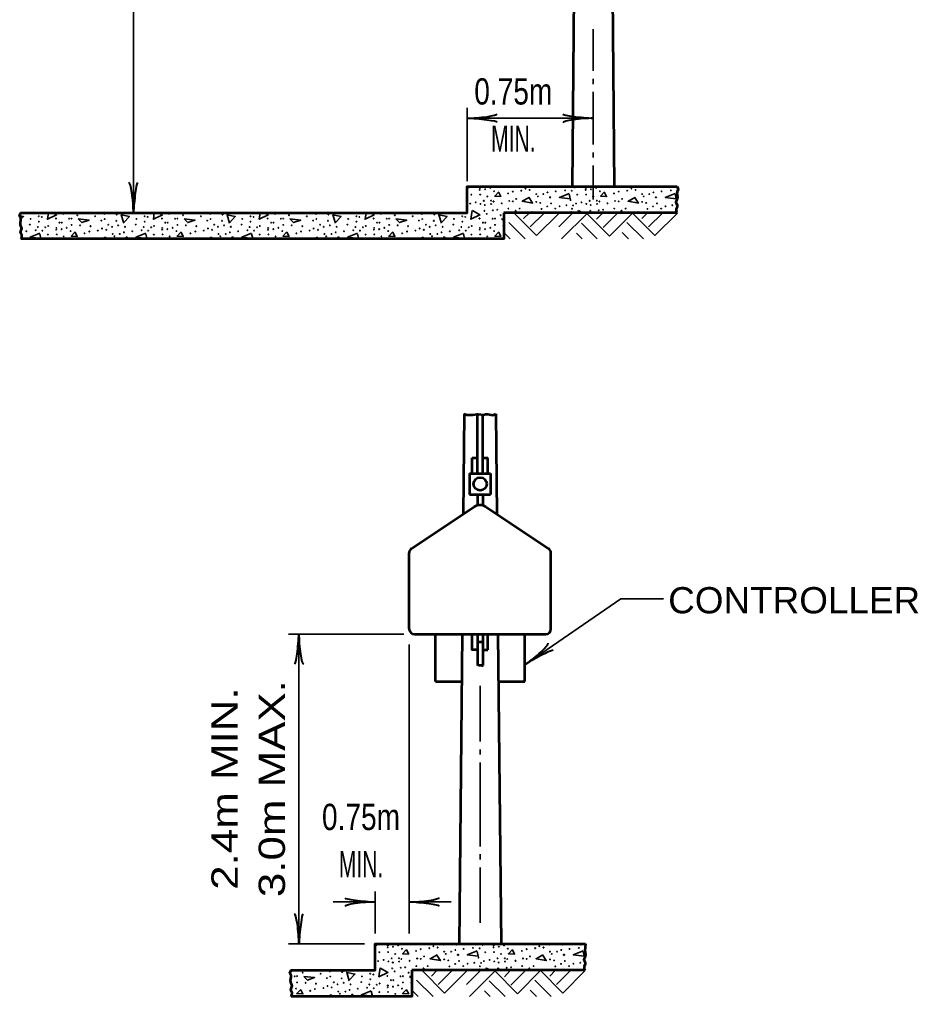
# Model space of a CAD drawing. Extents: x -35 to 821, y -10 to 534.
# Drawn here: x 462 to 564.7, y 213.3 to 325 of the extents above; entities that cross this region are included whole.
import ezdxf
from ezdxf.enums import TextEntityAlignment as Align

# ---------------------------------------------------------------- set-up
doc = ezdxf.new("R2010")
doc.units = 0
doc.header["$LTSCALE"] = 1.2
doc.layers.add('1', color=7, linetype='Continuous', lineweight=35)

msp = doc.modelspace()

# ---------------------------------------------------------------- linework, layer by layer
at = {"layer": '1', "lineweight": 53}
for p, q in [((526.127, 418.446), (525.086, 305.947)), ((528.844, 418.446), (529.886, 305.947)), ((537.086, 302.947), (517.286, 302.947)), ((512.767, 279.947), (512.653, 268.495)), ((514.267, 273.129), (514.267, 279.904)), ((514.867, 273.129), (514.867, 279.781)), ((516.367, 279.947), (516.48, 268.495)), ((513.667, 273.129), (513.667, 274.929)), ((513.667, 274.929), (514.267, 274.929)), ((514.867, 274.929), (515.467, 274.929)), ((515.467, 273.129), (515.467, 274.929)), ((513.367, 273.129), (515.767, 273.129)), ((513.367, 273.129), (513.367, 270.729)), ((515.767, 273.129), (515.767, 270.729)), ((513.367, 270.729), (515.767, 270.729)), ((514.267, 270.729), (514.267, 269.491)), ((514.867, 270.729), (514.867, 269.491)), ((506.734, 264.549), (513.901, 269.327)), ((515.232, 269.327), (522.399, 264.549)), ((506.467, 255.371), (506.467, 264.05)), ((522.667, 255.371), (522.667, 264.05)), ((507.067, 254.771), (522.067, 254.771)), ((509.467, 249.371), (509.467, 254.771)), ((512.517, 254.771), (512.167, 219.347)), ((514.267, 254.771), (514.267, 251.171)), ((514.867, 254.771), (514.867, 251.171)), ((515.467, 252.971), (515.467, 254.771)), ((516.616, 254.771), (516.967, 219.347)), ((519.667, 249.371), (519.667, 254.771)), ((514.267, 253.871), (514.867, 253.871)), ((514.867, 252.971), (515.467, 252.971)), ((509.467, 249.371), (512.464, 249.371)), ((516.669, 249.371), (519.667, 249.371)), ((526.567, 216.347), (506.767, 216.347))]:
    msp.add_line(p, q, dxfattribs=at)
at = {"layer": '1'}
for p, q in [((474.969, 394.147), (474.969, 302.947)), ((527.486, 319.147), (527.486, 323.947)), ((527.486, 317.647), (527.486, 318.247)), ((527.486, 310.747), (527.486, 316.747)), ((513.086, 306.547), (513.086, 314.947)), ((513.086, 313.747), (527.486, 313.747)), ((527.486, 309.247), (527.486, 309.847)), ((527.486, 308.347), (527.486, 304.447)), ((518.462, 302.899), (521.03, 300.331)), ((520.166, 302.899), (519.542, 302.275)), ((521.894, 302.899), (520.31, 301.315)), ((523.598, 302.899), (521.03, 300.331)), ((525.134, 302.899), (523.55, 301.315)), ((526.838, 302.899), (523.886, 299.947)), ((525.73, 302.947), (525.767, 303.207)), ((525.815, 303.183), (526.227, 302.947)), ((526.718, 302.899), (529.358, 300.259)), ((528.542, 302.899), (527.87, 302.203)), ((530.27, 302.899), (528.614, 301.243)), ((531.974, 302.899), (529.358, 300.259)), ((531.974, 302.899), (534.542, 300.331)), ((533.678, 302.899), (533.054, 302.275)), ((535.406, 302.899), (533.822, 301.315)), ((537.11, 302.899), (534.542, 300.331)), ((517.031, 302.247), (517.286, 302.217)), ((517.286, 301.992), (517.031, 302.247)), ((517.838, 301.819), (519.71, 299.947)), ((526.142, 301.747), (527.962, 299.947)), ((531.35, 301.819), (533.222, 299.947)), ((517.286, 300.667), (518.006, 299.947)), ((525.59, 300.595), (526.238, 299.947)), ((530.798, 300.667), (531.518, 299.947)), ((471.791, 300.135), (471.447, 299.947)), ((471.879, 299.947), (471.743, 300.159)), ((483.887, 300.135), (483.543, 299.947)), ((483.975, 299.947), (483.839, 300.159)), ((495.983, 300.135), (495.639, 299.947)), ((496.071, 299.947), (495.935, 300.159)), ((508.079, 300.135), (507.735, 299.947)), ((508.167, 299.947), (508.031, 300.159)), ((505.867, 254.771), (492.667, 254.771)), ((493.867, 254.771), (493.867, 219.347)), ((506.467, 253.571), (506.467, 220.547)), ((514.595, 242.496), (514.595, 248.846)), ((514.595, 240.996), (514.595, 241.597)), ((514.595, 230.496), (514.595, 240.097)), ((514.595, 228.996), (514.595, 229.597)), ((514.595, 221.747), (514.595, 228.097)), ((502.567, 220.547), (502.567, 225.347)), ((497.767, 224.147), (502.567, 224.147)), ((506.467, 224.147), (511.267, 224.147)), ((501.367, 219.347), (492.667, 219.347)), ((506.512, 215.647), (506.767, 215.617)), ((506.767, 215.392), (506.512, 215.647)), ((507.943, 216.299), (510.511, 213.731)), ((509.647, 216.299), (509.023, 215.675)), ((511.375, 216.299), (509.791, 214.715)), ((513.079, 216.299), (510.511, 213.731)), ((514.615, 216.299), (513.031, 214.715)), ((516.319, 216.299), (513.367, 213.347)), ((515.211, 216.347), (515.248, 216.607)), ((515.296, 216.583), (515.708, 216.347)), ((516.199, 216.299), (518.839, 213.659)), ((518.023, 216.299), (517.351, 215.603)), ((519.751, 216.299), (518.095, 214.643)), ((521.455, 216.299), (518.839, 213.659)), ((521.455, 216.299), (524.023, 213.731)), ((523.159, 216.299), (522.535, 215.675)), ((524.887, 216.299), (523.303, 214.715)), ((526.591, 216.299), (524.023, 213.731)), ((507.319, 215.219), (509.191, 213.347)), ((515.623, 215.147), (517.442, 213.347)), ((520.831, 215.219), (522.703, 213.347)), ((497.56, 213.535), (497.216, 213.347)), ((497.648, 213.347), (497.512, 213.559)), ((506.767, 214.067), (507.487, 213.347)), ((515.071, 213.995), (515.719, 213.347)), ((520.279, 214.067), (520.999, 213.347))]:
    msp.add_line(p, q, dxfattribs=at)
at = {"layer": '1', "lineweight": 53}
for points in [[(462.086, 299.947), (462.195, 300.105), (462.202, 300.36), (462.071, 300.655), (462.09, 300.825), (462.228, 301.152), (462.077, 301.564), (462.045, 301.754), (462.11, 302.16), (462.09, 302.35), (461.953, 302.605), (462.086, 302.947), (513.086, 302.947), (513.086, 305.947), (537.086, 305.947)], [(537.086, 305.947), (537.219, 305.605), (537.082, 305.35), (537.062, 305.16), (537.127, 304.754), (537.095, 304.564), (536.944, 304.152), (537.082, 303.825), (537.101, 303.655), (536.97, 303.36), (536.977, 303.105), (537.086, 302.947)], [(517.286, 302.947), (517.286, 299.947), (462.086, 299.947)], [(512.767, 279.947), (513.075, 279.853), (513.714, 279.843), (513.733, 279.843), (514.23, 279.9), (514.362, 279.909), (514.991, 279.825), (515.207, 279.9), (515.441, 279.909), (516.023, 279.797), (516.367, 279.947)], [(514.267, 252.971), (513.667, 252.971), (513.667, 254.771)], [(514.267, 251.171), (514.351, 251.263), (514.495, 251.202), (514.53, 251.202), (514.647, 251.202), (514.688, 251.215), (514.763, 251.215), (514.832, 251.16), (514.867, 251.171)], [(492.967, 213.347), (493.076, 213.505), (493.082, 213.76), (492.952, 214.055), (492.971, 214.225), (493.109, 214.552), (492.958, 214.964), (492.925, 215.154), (492.991, 215.56), (492.971, 215.75), (492.834, 216.005), (492.967, 216.347), (502.567, 216.347), (502.567, 219.347), (526.624, 219.347)], [(526.624, 219.347), (526.543, 218.56), (526.608, 218.154), (526.575, 217.964), (526.425, 217.552), (526.562, 217.225), (526.582, 217.055), (526.451, 216.76), (526.458, 216.505), (526.567, 216.347)], [(506.767, 216.347), (506.767, 213.347), (492.967, 213.347)]]:
    msp.add_lwpolyline(points, dxfattribs=at)
at = {"layer": '1'}
for points in [[(516.695, 305.319), (516.239, 304.839), (516.935, 304.791), (516.695, 305.271)], [(524.759, 305.151), (523.631, 304.695), (524.879, 304.55), (524.759, 305.103)], [(528.791, 305.319), (528.335, 304.839), (529.031, 304.791), (528.791, 305.271)], [(536.855, 305.151), (535.727, 304.695), (536.975, 304.55), (536.855, 305.103)], [(520.175, 304.695), (519.383, 304.262), (520.559, 304.047), (520.127, 304.719)], [(532.271, 304.695), (531.479, 304.262), (532.655, 304.047), (532.223, 304.719)], [(465.747, 302.947), (466.175, 302.702), (465.143, 302.199), (465.25, 302.947)], [(473.855, 301.743), (473.567, 302.702), (474.503, 302.511), (473.831, 301.791)], [(477.843, 302.947), (478.271, 302.702), (477.239, 302.199), (477.346, 302.947)], [(485.951, 301.743), (485.663, 302.702), (486.599, 302.511), (485.927, 301.791)], [(489.939, 302.947), (490.367, 302.702), (489.335, 302.199), (489.442, 302.947)], [(498.047, 301.743), (497.759, 302.702), (498.695, 302.511), (498.023, 301.791)], [(502.035, 302.947), (502.463, 302.702), (501.431, 302.199), (501.538, 302.947)], [(510.143, 301.743), (509.855, 302.702), (510.791, 302.511), (510.119, 301.791)], [(513.719, 303.183), (514.559, 302.702), (513.527, 302.199), (513.671, 303.207)], [(461.954, 302.603), (462.407, 302.511), (462.107, 302.189)], [(464.279, 300.591), (463.151, 300.135), (464.399, 299.99), (464.279, 300.543)], [(468.311, 300.759), (467.855, 300.279), (468.551, 300.231), (468.311, 300.711)], [(476.375, 300.591), (475.247, 300.135), (476.495, 299.99), (476.375, 300.543)], [(480.407, 300.759), (479.951, 300.279), (480.647, 300.231), (480.407, 300.711)], [(488.471, 300.591), (487.343, 300.135), (488.591, 299.99), (488.471, 300.543)], [(492.503, 300.759), (492.047, 300.279), (492.743, 300.231), (492.503, 300.711)], [(500.567, 300.591), (499.439, 300.135), (500.687, 299.99), (500.567, 300.543)], [(504.599, 300.759), (504.143, 300.279), (504.839, 300.231), (504.599, 300.711)], [(512.663, 300.591), (511.535, 300.135), (512.783, 299.99), (512.663, 300.543)], [(516.695, 300.759), (516.239, 300.279), (516.935, 300.231), (516.695, 300.711)], [(519.788, 251.341), (530.66, 258.795), (535.524, 258.795)], [(506.176, 218.719), (505.72, 218.239), (506.416, 218.191), (506.176, 218.671)], [(509.656, 218.095), (508.864, 217.663), (510.04, 217.447), (509.608, 218.119)], [(514.24, 218.551), (513.112, 218.095), (514.36, 217.951), (514.24, 218.503)], [(518.272, 218.719), (517.816, 218.239), (518.512, 218.191), (518.272, 218.671)], [(521.752, 218.095), (520.96, 217.663), (522.136, 217.447), (521.704, 218.119)], [(526.336, 218.551), (525.208, 218.095), (526.456, 217.951), (526.336, 218.503)], [(499.624, 215.143), (499.336, 216.103), (500.272, 215.911), (499.6, 215.191)], [(503.2, 216.583), (504.04, 216.103), (503.008, 215.599), (503.152, 216.607)], [(494.08, 214.159), (493.624, 213.679), (494.32, 213.631), (494.08, 214.111)], [(502.144, 213.991), (501.016, 213.535), (502.264, 213.391), (502.144, 213.943)], [(506.176, 214.159), (505.72, 213.679), (506.416, 213.631), (506.176, 214.111)]]:
    msp.add_lwpolyline(points, dxfattribs=at)
for points in [[(468.647, 302.247), (469.895, 302.103), (469.079, 301.815)], [(480.743, 302.247), (481.991, 302.103), (481.175, 301.815)], [(492.839, 302.247), (494.087, 302.103), (493.271, 301.815)], [(504.935, 302.247), (506.183, 302.103), (505.367, 301.815)], [(494.416, 215.647), (495.664, 215.503), (494.848, 215.215)]]:
    msp.add_lwpolyline(points, close=True, dxfattribs=at)
for centre in [(513.278, 305.843), (513.58, 305.005), (514.534, 305.562), (514.55, 305.763), (514.582, 305.021), (515.139, 305.626), (515.727, 305.779), (516.166, 305.403), (517.772, 305.149), (518.313, 305.355), (519.283, 305.467), (519.76, 305.7), (520.237, 305.546), (520.905, 305.89), (520.985, 305.069), (521.796, 305.069), (522.273, 305.26), (522.384, 305.89), (523.211, 305.387), (524.277, 305.499), (524.531, 305.875), (525.04, 305.451), (525.374, 305.843), (525.676, 305.005), (526.63, 305.562), (526.646, 305.763), (526.678, 305.021), (527.235, 305.626), (527.823, 305.779), (528.262, 305.403), (529.868, 305.149), (530.409, 305.355), (531.379, 305.467), (531.856, 305.7), (532.333, 305.546), (533.001, 305.89), (533.081, 305.069), (533.892, 305.069), (534.369, 305.26), (534.48, 305.89), (535.307, 305.387), (536.373, 305.499), (536.627, 305.875), (513.437, 303.987), (514.073, 304.13), (514.614, 303.955), (514.996, 304.305), (515.123, 303.828), (515.393, 304.799), (515.823, 304.321), (515.839, 303.939), (516.102, 304.226), (517.04, 304.019), (517.899, 304.289), (518.313, 304.242), (518.694, 304.528), (520.985, 304.178), (521.175, 304.814), (521.446, 304.067), (522.543, 304.703), (522.607, 304.703), (522.686, 304.003), (524.436, 303.796), (524.913, 304.385), (525.199, 303.78), (525.533, 303.987), (526.169, 304.13), (526.71, 303.955), (527.092, 304.305), (527.219, 303.828), (527.489, 304.799), (527.919, 304.321), (527.935, 303.939), (528.198, 304.226), (529.136, 304.019), (529.995, 304.289), (530.409, 304.242), (530.79, 304.528), (533.081, 304.178), (533.271, 304.814), (533.542, 304.067), (534.639, 304.703), (534.703, 304.703), (534.782, 304.003), (536.532, 303.796), (466.946, 302.81), (468.545, 302.667), (471.63, 302.81), (473.046, 302.73), (479.042, 302.81), (480.641, 302.667), (483.726, 302.81), (485.142, 302.73), (491.138, 302.81), (492.737, 302.667), (495.822, 302.81), (497.238, 302.73), (503.234, 302.81), (504.833, 302.667), (507.918, 302.81), (509.334, 302.73), (515.059, 303.16), (515.33, 302.81), (516.029, 303.224), (516.532, 303.287), (516.929, 302.667), (517.804, 303.414), (518.631, 303.16), (519.108, 303.414), (520.507, 303.017), (521.589, 303.383), (522.241, 303.669), (523.163, 303.414), (523.656, 303.685), (524.992, 303.033), (525.072, 303.399), (527.155, 303.16), (528.125, 303.224), (528.628, 303.287), (529.9, 303.414), (530.727, 303.16), (531.204, 303.414), (532.603, 303.017), (533.685, 303.383), (534.337, 303.669), (535.259, 303.414), (535.752, 303.685), (463.129, 301.585), (463.208, 302.237), (464.147, 302.539), (464.163, 301.919), (464.496, 302.46), (466.119, 302.285), (466.516, 301.808), (466.787, 301.808), (467.622, 302.25), (467.893, 302.269), (467.893, 301.553), (470.581, 302.539), (471.297, 302.046), (471.678, 302.221), (472.092, 301.569), (472.998, 302.014), (475.225, 301.585), (475.304, 302.237), (476.243, 302.539), (476.259, 301.919), (476.592, 302.46), (478.215, 302.285), (478.612, 301.808), (478.883, 301.808), (479.718, 302.25), (479.989, 302.269), (479.989, 301.553), (482.677, 302.539), (483.393, 302.046), (483.774, 302.221), (484.188, 301.569), (485.094, 302.014), (487.321, 301.585), (487.4, 302.237), (488.339, 302.539), (488.355, 301.919), (488.688, 302.46), (490.311, 302.285), (490.708, 301.808), (490.979, 301.808), (491.814, 302.25), (492.085, 302.269), (492.085, 301.553), (494.773, 302.539), (495.489, 302.046), (495.87, 302.221), (496.284, 301.569), (497.19, 302.014), (499.417, 301.585), (499.496, 302.237), (500.435, 302.539), (500.451, 301.919), (500.784, 302.46), (502.407, 302.285), (502.804, 301.808), (503.075, 301.808), (503.91, 302.25), (504.181, 302.269), (504.181, 301.553), (506.869, 302.539), (507.585, 302.046), (507.966, 302.221), (508.38, 301.569), (509.286, 302.014), (511.513, 301.585), (511.592, 302.237), (512.531, 302.539), (512.547, 301.919), (512.88, 302.46), (514.503, 302.285), (514.9, 301.808), (515.171, 301.808), (516.006, 302.25), (516.277, 302.269), (516.277, 301.553), (462.731, 300.827), (463.797, 300.939), (464.051, 301.315), (464.56, 300.891), (464.894, 301.283), (465.196, 300.445), (465.228, 301.426), (466.15, 301.002), (466.166, 301.203), (466.198, 300.461), (466.755, 301.066), (467.343, 301.219), (467.782, 300.843), (468.863, 301.505), (469.388, 300.589), (469.929, 300.795), (470.056, 301.41), (470.899, 300.907), (471.376, 301.14), (471.853, 300.986), (472.521, 301.33), (472.601, 300.509), (473.221, 301.505), (473.412, 300.509), (473.889, 300.7), (474, 301.33), (474.827, 300.827), (475.893, 300.939), (476.147, 301.315), (476.656, 300.891), (476.99, 301.283), (477.292, 300.445), (477.324, 301.426), (478.246, 301.002), (478.262, 301.203), (478.294, 300.461), (478.851, 301.066), (479.439, 301.219), (479.878, 300.843), (480.959, 301.505), (481.484, 300.589), (482.025, 300.795), (482.152, 301.41), (482.995, 300.907), (483.472, 301.14), (483.949, 300.986), (484.617, 301.33), (484.697, 300.509), (485.317, 301.505), (485.508, 300.509), (485.985, 300.7), (486.096, 301.33), (486.923, 300.827), (487.989, 300.939), (488.243, 301.315), (488.752, 300.891), (489.086, 301.283), (489.388, 300.445), (489.42, 301.426), (490.342, 301.002), (490.358, 301.203), (490.39, 300.461), (490.947, 301.066), (491.535, 301.219), (491.974, 300.843), (493.055, 301.505), (493.58, 300.589), (494.121, 300.795), (494.248, 301.41), (495.091, 300.907), (495.568, 301.14), (496.045, 300.986), (496.713, 301.33), (496.793, 300.509), (497.413, 301.505), (497.604, 300.509), (498.081, 300.7), (498.192, 301.33), (499.019, 300.827), (500.085, 300.939), (500.339, 301.315), (500.848, 300.891), (501.182, 301.283), (501.484, 300.445), (501.516, 301.426), (502.438, 301.002), (502.454, 301.203), (502.486, 300.461), (503.043, 301.066), (503.631, 301.219), (504.07, 300.843), (505.151, 301.505), (505.676, 300.589), (506.217, 300.795), (506.344, 301.41), (507.187, 300.907), (507.664, 301.14), (508.141, 300.986), (508.809, 301.33), (508.889, 300.509), (509.509, 301.505), (509.7, 300.509), (510.177, 300.7), (510.288, 301.33), (511.115, 300.827), (512.181, 300.939), (512.435, 301.315), (512.944, 300.891), (513.278, 301.283), (513.58, 300.445), (513.612, 301.426), (514.534, 301.002), (514.55, 301.203), (514.582, 300.461), (515.139, 301.066), (515.727, 301.219), (516.166, 300.843), (517.247, 301.505), (467.009, 300.239), (472.791, 300.254), (474.159, 300.143), (474.223, 300.143), (479.105, 300.239), (484.887, 300.254), (486.255, 300.143), (486.319, 300.143), (491.201, 300.239), (496.983, 300.254), (498.351, 300.143), (498.415, 300.143), (503.297, 300.239), (509.079, 300.254), (510.447, 300.143), (510.511, 300.143), (515.393, 300.239), (502.759, 219.243), (504.015, 218.962), (504.031, 219.163), (504.619, 219.026), (505.208, 219.179), (508.764, 218.867), (509.241, 219.1), (509.718, 218.946), (510.386, 219.29), (511.865, 219.29), (513.757, 218.899), (514.012, 219.275), (514.855, 219.243), (516.111, 218.962), (516.127, 219.163), (516.715, 219.026), (517.304, 219.179), (520.86, 218.867), (521.337, 219.1), (521.814, 218.946), (522.482, 219.29), (523.961, 219.29), (525.853, 218.899), (526.108, 219.275), (503.061, 218.405), (504.063, 218.421), (504.874, 218.199), (505.647, 218.803), (507.253, 218.549), (507.794, 218.755), (508.175, 217.928), (510.465, 218.469), (510.656, 218.214), (511.276, 218.469), (511.754, 218.66), (512.024, 218.103), (512.088, 218.103), (512.692, 218.787), (514.394, 217.785), (514.521, 218.851), (515.157, 218.405), (516.159, 218.421), (516.97, 218.199), (517.743, 218.803), (519.349, 218.549), (519.89, 218.755), (520.271, 217.928), (522.561, 218.469), (522.752, 218.214), (523.372, 218.469), (523.85, 218.66), (524.12, 218.103), (524.184, 218.103), (524.788, 218.787), (502.918, 217.387), (503.554, 217.53), (504.095, 217.355), (504.476, 217.705), (504.604, 217.228), (505.303, 217.721), (505.319, 217.34), (505.583, 217.626), (506.012, 216.687), (506.521, 217.419), (507.285, 216.815), (507.38, 217.69), (507.794, 217.642), (508.589, 216.815), (510.465, 217.578), (510.927, 217.467), (511.07, 216.783), (511.722, 217.069), (512.167, 217.403), (512.644, 216.815), (513.137, 217.085), (513.916, 217.196), (514.553, 216.799), (514.68, 217.18), (515.014, 217.387), (515.65, 217.53), (516.191, 217.355), (516.572, 217.705), (516.7, 217.228), (517.399, 217.721), (517.415, 217.34), (517.679, 217.626), (518.108, 216.687), (518.617, 217.419), (519.381, 216.815), (519.476, 217.69), (519.89, 217.642), (520.685, 216.815), (522.561, 217.578), (523.023, 217.467), (523.166, 216.783), (523.818, 217.069), (524.263, 217.403), (524.74, 216.815), (525.233, 217.085), (526.012, 217.196), (493.39, 215.651), (493.662, 215.669), (494.314, 216.067), (496.35, 215.94), (497.399, 216.21), (497.447, 215.621), (498.815, 216.13), (501.073, 215.637), (502.011, 215.94), (502.361, 215.86), (503.983, 215.685), (504.54, 216.56), (504.81, 216.21), (505.486, 215.651), (505.51, 216.624), (505.758, 215.669), (506.41, 216.067), (508.112, 216.56), (509.988, 216.417), (514.473, 216.433), (516.636, 216.56), (517.606, 216.624), (520.208, 216.56), (522.084, 216.417), (493.112, 214.619), (493.662, 214.953), (494.632, 214.906), (495.825, 214.81), (497.065, 215.446), (497.145, 214.54), (497.86, 214.969), (498.29, 214.73), (498.767, 215.415), (498.99, 214.906), (499.769, 214.73), (500.993, 214.985), (501.916, 214.715), (502.027, 215.319), (502.759, 214.683), (503.093, 214.826), (504.015, 214.402), (504.031, 214.603), (504.381, 215.208), (504.619, 214.466), (504.651, 215.208), (505.208, 214.619), (505.758, 214.953), (506.728, 214.906), (493.551, 214.243), (495.157, 213.989), (495.698, 214.195), (496.668, 214.307), (497.622, 214.386), (498.369, 213.909), (498.56, 213.654), (499.18, 213.909), (499.658, 214.1), (499.928, 213.543), (499.992, 213.543), (500.596, 214.227), (501.661, 214.339), (502.425, 214.291), (503.061, 213.845), (504.063, 213.861), (504.874, 213.639), (505.647, 214.243)]:
    msp.add_circle(centre, 0.0318, dxfattribs=at)
at = {"layer": '1', "lineweight": 53}
msp.add_circle((514.581, 271.941), 0.75, dxfattribs=at)
at = {"layer": '1'}
for centre, start, end in [((518.44, 305.97), 226.35082, 313.64918), ((530.536, 305.97), 226.35082, 313.64918), ((537.136, 305.451), 61.61934, 241.7845), ((513.103, 303.78), 237.37076, 122.62924), ((537.009, 304.385), 32.83014, 287.06312), ((463.017, 302.969), 223.9797, 316.0203), ((463.638, 302.937), 162.01481, 17.98519), ((469.356, 302.937), 162.01481, 17.98519), ((475.113, 302.969), 223.9797, 316.0203), ((475.734, 302.937), 162.01481, 17.98519), ((481.452, 302.937), 162.01481, 17.98519), ((487.209, 302.969), 223.9797, 316.0203), ((487.83, 302.937), 162.01481, 17.98519), ((493.548, 302.937), 162.01481, 17.98519), ((499.305, 302.969), 223.9797, 316.0203), ((499.926, 302.937), 162.01481, 17.98519), ((505.644, 302.937), 162.01481, 17.98519), ((511.401, 302.969), 223.9797, 316.0203), ((512.022, 302.937), 162.01481, 17.98519), ((517.74, 302.937), 17.98519, 162.01481), ((523.497, 302.969), 316.0203, 223.9797), ((524.118, 302.937), 17.98519, 162.01481), ((529.836, 302.937), 17.98519, 162.01481), ((535.593, 302.969), 316.0203, 223.9797), ((536.214, 302.937), 17.98519, 162.01481), ((470.31, 299.968), 318.30023, 221.69977), ((482.406, 299.968), 318.30023, 221.69977), ((494.502, 299.968), 318.30023, 221.69977), ((506.598, 299.968), 318.30023, 221.69977), ((507.921, 219.37), 226.35082, 313.64918), ((520.017, 219.37), 226.35082, 313.64918), ((526.49, 217.785), 32.83014, 287.06312), ((526.617, 218.851), 61.61934, 241.7845), ((502.584, 217.18), 237.37076, 122.62924), ((495.125, 216.337), 162.01481, 17.98519), ((500.882, 216.369), 223.9797, 316.0203), ((501.502, 216.337), 162.01481, 17.98519), ((507.221, 216.337), 17.98519, 162.01481), ((512.978, 216.369), 316.0203, 223.9797), ((513.598, 216.337), 17.98519, 162.01481), ((519.317, 216.337), 17.98519, 162.01481), ((525.074, 216.369), 316.0203, 223.9797), ((525.694, 216.337), 17.98519, 162.01481), ((496.079, 213.368), 318.30023, 221.69977)]:
    msp.add_arc(centre, 0.0318, start, end, dxfattribs=at)
at = {"layer": '1', "lineweight": 53}
for centre, radius, start, end in [((514.567, 268.329), 1.2, 56.30808, 123.69007), ((507.067, 264.05), 0.6, 123.69239, 180), ((522.067, 264.05), 0.6, 0, 56.30661), ((507.067, 255.371), 0.6, 180, 270), ((522.067, 255.371), 0.6, 270, 0)]:
    msp.add_arc(centre, radius, start, end, dxfattribs=at)
at = {"layer": '1', "lineweight": 40}
for centre, major_axis, ratio, start_param, end_param in [((514.395, 314.079), (-2.143, -0.187), 0.122415, 0.8963533, 3.1415927), ((514.395, 314.079), (-2.143, -0.187), 0.122415, 0.8963533, 3.1415927), ((526.141, 314.001), (2.108, -0.211), 0.07063, 3.1407148, 5.41811), ((514.431, 313.493), (-2.108, 0.211), 0.07063, 3.1407148, 5.41811), ((514.431, 313.493), (-2.108, 0.211), 0.07063, 3.1407148, 5.41811), ((526.177, 313.415), (2.143, 0.187), 0.122415, 0.8963533, 3.1415927), ((474.638, 304.256), (0.187, -2.143), 0.122415, 0.8963533, 3.1415927), ((475.223, 304.292), (-0.211, -2.108), 0.07063, 3.1407148, 5.41811), ((493.613, 253.426), (0.211, 2.108), 0.07063, 3.1407148, 5.41811), ((493.613, 253.426), (0.211, 2.108), 0.07063, 3.1407148, 5.41811), ((494.198, 253.462), (-0.187, 2.143), 0.122415, 0.8963533, 3.1415927), ((494.198, 253.462), (-0.187, 2.143), 0.122415, 0.8963533, 3.1415927), ((520.68, 252.355), (-1.661, -1.366), 0.122415, 0.8963533, 3.1415927), ((520.68, 252.355), (-1.661, -1.366), 0.122415, 0.8963533, 3.1415927), ((521.041, 251.892), (1.858, 1.018), 0.07063, 6.2823074, 8.5597026), ((521.041, 251.892), (1.858, 1.018), 0.07063, 6.2823074, 8.5597026), ((501.222, 224.401), (2.108, -0.211), 0.07063, 3.1407148, 5.41811), ((501.222, 224.401), (2.108, -0.211), 0.07063, 3.1407148, 5.41811), ((507.776, 224.479), (-2.143, -0.187), 0.122415, 0.8963533, 3.1415927), ((507.776, 224.479), (-2.143, -0.187), 0.122415, 0.8963533, 3.1415927), ((501.257, 223.816), (2.143, 0.187), 0.122415, 0.8963533, 3.1415927), ((501.257, 223.816), (2.143, 0.187), 0.122415, 0.8963533, 3.1415927), ((507.811, 223.893), (-2.108, 0.211), 0.07063, 3.1407148, 5.41811), ((507.811, 223.893), (-2.108, 0.211), 0.07063, 3.1407148, 5.41811), ((493.535, 220.657), (0.187, -2.143), 0.122415, 0.8963533, 3.1415927), ((494.121, 220.692), (-0.211, -2.108), 0.07063, 3.1407148, 5.41811)]:
    msp.add_ellipse(centre, major_axis=major_axis, ratio=ratio, start_param=start_param, end_param=end_param, dxfattribs=at)

# ---------------------------------------------------------------- texts
at = {"layer": '1'}
for s, width, p in [('0.75m', 0.8, (518.366, 315.312)), ('MIN.', 0.6, (518.366, 309.912)), ('0.75m', 0.8, (500.966, 232.373)), ('MIN.', 0.6, (500.966, 226.973))]:
    msp.add_text(s, height=3, dxfattribs=dict(at, width=width)).set_placement(p, align=Align.CENTER)
at = {"layer": '1', "width": 1.05}
msp.add_text('CONTROLLER', height=3, dxfattribs=at).set_placement((536.061, 257.144))
at = {"layer": '1', "width": 1.25}
for s, p in [('2.4m MIN.', (486.876, 237.105)), ('3.0m MAX.', (492.276, 237.105))]:
    msp.add_text(s, height=3, rotation=90, dxfattribs=at).set_placement(p, align=Align.CENTER)

doc.saveas('drawing.dxf')
